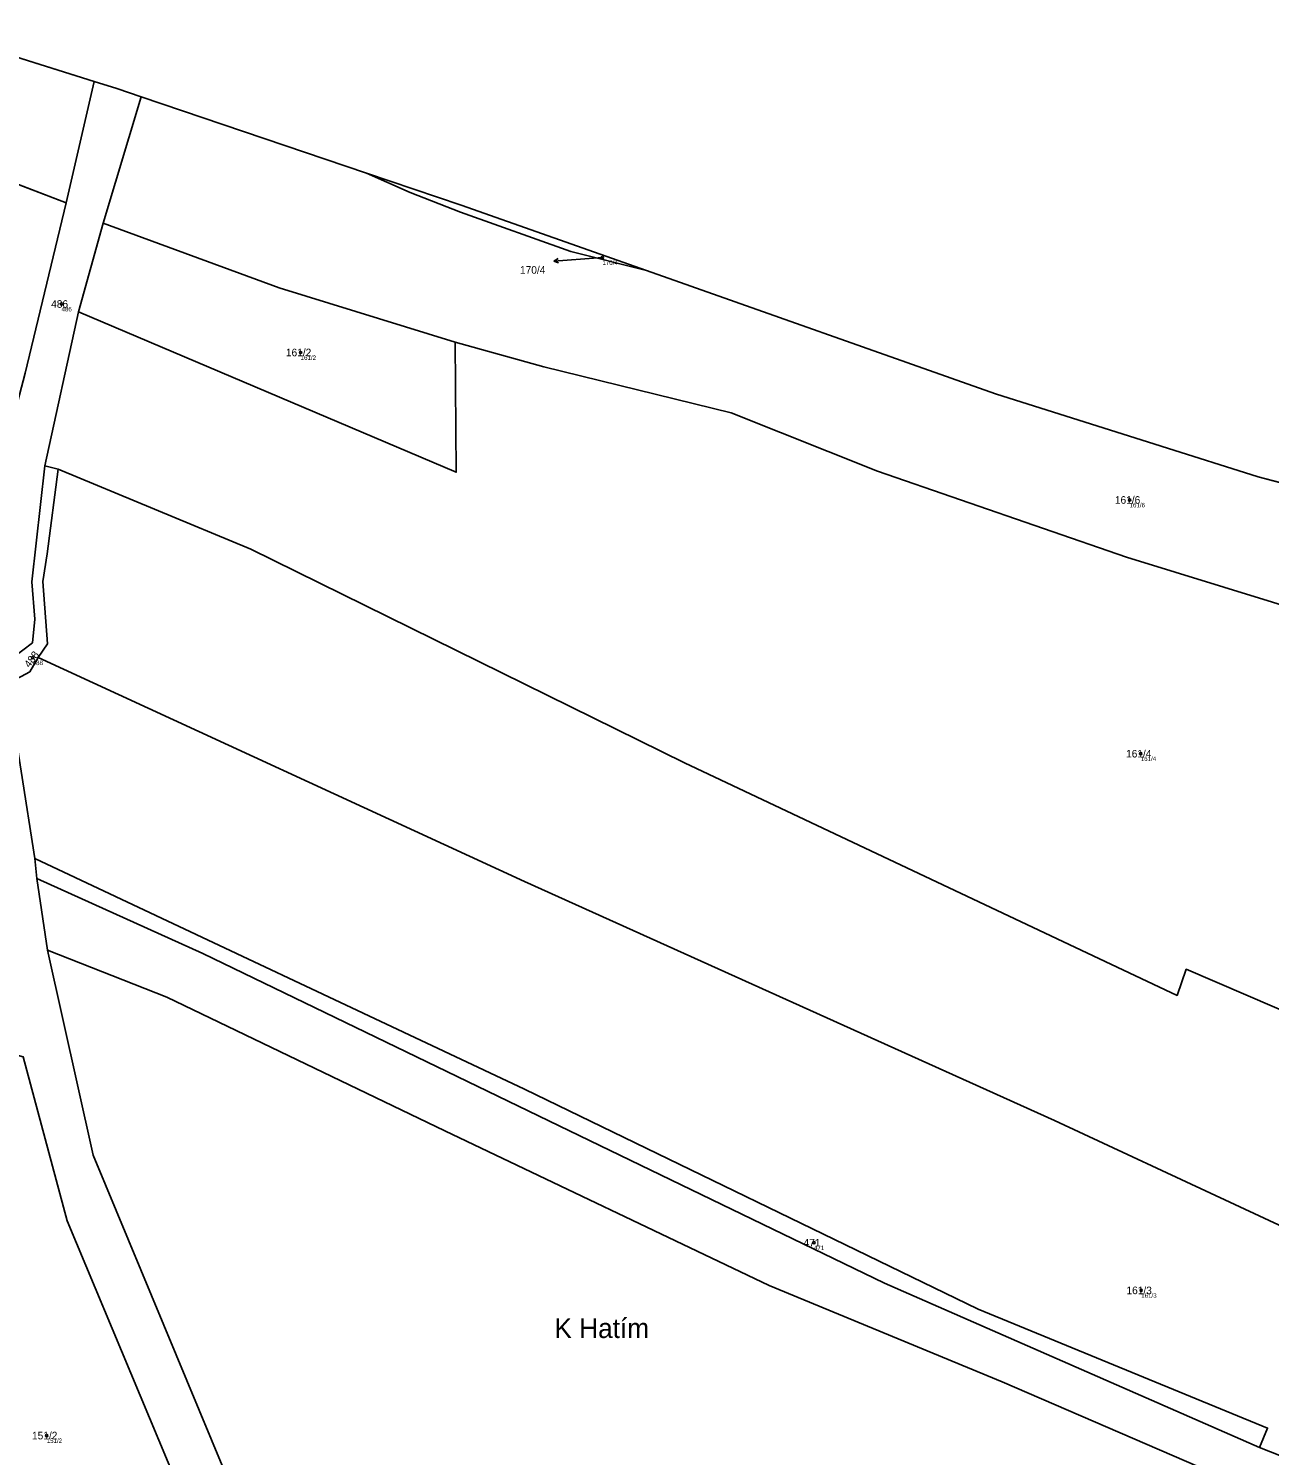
# Model space of a CAD drawing. Extents: x -700238 to -698499, y -1070626 to -1068006.
# Drawn here: x -700094 to -699815.7, y -1068332.5 to -1068012.6 of the extents above; entities that cross this region are included whole.
import ezdxf

# ---------------------------------------------------------------- set-up
doc = ezdxf.new("R2010")
doc.units = 0
for name, color, linetype in [('Definiční body', 7, 'Continuous'), ('Hranice parcel', 7, 'Continuous'), ('Parcelní čísla', 7, 'Continuous'), ('Polygon ku', 7, 'Continuous'), ('Polygon parcely', 7, 'Continuous'), ('Pop  PČ popisy', 7, 'Continuous')]:
    doc.layers.add(name, color=color, linetype=linetype)

msp = doc.modelspace()

# ---------------------------------------------------------------- linework, layer by layer
at = {"layer": 'Definiční body'}
for centre in [(-699965.3, -1068063.93994), (-700086.61, -1068074.34994), (-700032.98, -1068085.22994), (-699847.05, -1068118.28994), (-700093.08, -1068153.66994), (-699844.55, -1068175.18994), (-699917.85, -1068284.82994), (-699844.45, -1068295.52994), (-700089.93, -1068328.07994)]:
    msp.add_circle(centre, 0.25, dxfattribs=at)
at = {"layer": 'Hranice parcel'}
for p, q in [((-700079.26, -1068024.45), (-700117.11, -1068012.59)), ((-700079.26, -1068024.45), (-700085.54, -1068051.67)), ((-700077.24, -1068056.21), (-700068.77, -1068027.88)), ((-700068.77, -1068027.88), (-700018.24, -1068045.01)), ((-700085.54, -1068051.67), (-700125.51, -1068036.4)), ((-699996.96, -1068052.22), (-700018.24, -1068045.01)), ((-699955.42, -1068066.88), (-699996.96, -1068052.22)), ((-700082.81, -1068076.08), (-700077.24, -1068056.21)), ((-700090.39, -1068110.64), (-700082.81, -1068076.08)), ((-699818.2, -1068113.11), (-699840.01, -1068106.22)), ((-700087.38, -1068111.39), (-700090.39, -1068110.64)), ((-699778.25, -1068123.74), (-699818.2, -1068113.11)), ((-700092.58, -1068198.68), (-700098.76, -1068159.5)), ((-700092.18, -1068203.16), (-700092.58, -1068198.68)), ((-700089.79, -1068219.21), (-700092.18, -1068203.16))]:
    msp.add_line(p, q, dxfattribs=at)
for points in [[(-700068.77, -1068027.88), (-700074.2, -1068026.04), (-700079.26, -1068024.45)], [(-700018.24, -1068045.01), (-700008.41, -1068049.32), (-699997.14, -1068053.76), (-699972.36, -1068062.6), (-699955.42, -1068066.88)], [(-700099.51, -1068107.86), (-700094.74, -1068089.83), (-700085.54, -1068051.67)], [(-699998.31, -1068082.9), (-700037.79, -1068070.76), (-700077.24, -1068056.21)], [(-699955.42, -1068066.88), (-699877.11, -1068094.51), (-699840.01, -1068106.22)], [(-700082.81, -1068076.08), (-699998.06, -1068112.08), (-699998.31, -1068082.9)], [(-699612.1, -1068205.01), (-699704.91, -1068175.15), (-699847.75, -1068131.11), (-699903.56, -1068111.83), (-699936.42, -1068098.78), (-699978.4, -1068088.46), (-699998.31, -1068082.9)], [(-700099.66, -1068155.28), (-700093.15, -1068150.31), (-700092.59, -1068145.04), (-700093.29, -1068136.63), (-700090.39, -1068110.64)], [(-700091.82, -1068153.6), (-700089.78, -1068150.52), (-700090.77, -1068136.56), (-700089.86, -1068130.36), (-700087.38, -1068111.39)], [(-699647.05, -1068296.11), (-699722.11, -1068270.77), (-699760.47, -1068255.26), (-699834.34, -1068223.51), (-699836.42, -1068229.4), (-699946.86, -1068177.24), (-700044.14, -1068129.31), (-700087.38, -1068111.39)], [(-700098.76, -1068159.5), (-700093.72, -1068156.82), (-700091.82, -1068153.6)], [(-700091.82, -1068153.6), (-699982.79, -1068203.82), (-699863.89, -1068257.44), (-699783, -1068295.12), (-699698.72, -1068329.85), (-699635.57, -1068348.43), (-699608.73, -1068359.75)], [(-700092.58, -1068198.68), (-699982.77, -1068250.43), (-699881.04, -1068299.73), (-699816.11, -1068326.4), (-699817.93, -1068330.74)], [(-699817.93, -1068330.74), (-699901.99, -1068293.89), (-700054.94, -1068220), (-700092.18, -1068203.16)], [(-700047.78, -1068341.46), (-700079.51, -1068265.19), (-700089.79, -1068219.21)], [(-699627.99, -1068411.98), (-699659.02, -1068402.7), (-699710.69, -1068385.66), (-699740.56, -1068374.38), (-699875.66, -1068316.05), (-699927.93, -1068294.45), (-700000.63, -1068259.75), (-700062.96, -1068229.76), (-700089.79, -1068219.21)], [(-700040.88, -1068407.88), (-700044.5, -1068383.96), (-700052.63, -1068358.24), (-700085.32, -1068279.92), (-700095.19, -1068243.17)], [(-699623.95, -1068401.12), (-699708.94, -1068373.65), (-699817.93, -1068330.74)]]:
    msp.add_lwpolyline(points, dxfattribs=at)
at = {"layer": 'Polygon ku'}
msp.add_lwpolyline([(-699778.25, -1068123.74), (-699818.2, -1068113.11), (-699840.01, -1068106.22), (-699877.11, -1068094.51), (-699955.42, -1068066.88), (-699996.96, -1068052.22), (-700018.24, -1068045.01), (-700068.77, -1068027.88), (-700074.2, -1068026.04), (-700079.26, -1068024.45), (-700117.11, -1068012.59)], dxfattribs=at)
at = {"layer": 'Polygon parcely'}
for points in [[(-700079.26, -1068024.45), (-700117.11, -1068012.59), (-700126.53, -1068012.95), (-700125.51, -1068036.4), (-700085.54, -1068051.67)], [(-700068.77, -1068027.88), (-700074.2, -1068026.04), (-700079.26, -1068024.45), (-700085.54, -1068051.67), (-700094.74, -1068089.83), (-700099.51, -1068107.86), (-700107.22, -1068133.46), (-700099.66, -1068155.28), (-700093.15, -1068150.31), (-700092.59, -1068145.04), (-700093.29, -1068136.63), (-700090.39, -1068110.64), (-700082.81, -1068076.08), (-700077.24, -1068056.21)], [(-700106.82, -1068093.51), (-700104.41, -1068104.21), (-700112.08, -1068105.44), (-700099.51, -1068107.86), (-700094.74, -1068089.83), (-700085.54, -1068051.67), (-700125.51, -1068036.4), (-700117.1, -1068078.28), (-700110.86, -1068077.16), (-700109.59, -1068083.76), (-700115.86, -1068084.98), (-700114, -1068095.05)], [(-699955.42, -1068066.88), (-699996.96, -1068052.22), (-700018.24, -1068045.01), (-700008.41, -1068049.32), (-699997.14, -1068053.76), (-699972.36, -1068062.6)], [(-699998.31, -1068082.9), (-700037.79, -1068070.76), (-700077.24, -1068056.21), (-700082.81, -1068076.08), (-699998.06, -1068112.08)], [(-699847.75, -1068131.11), (-699903.56, -1068111.83), (-699936.42, -1068098.78), (-699978.4, -1068088.46), (-699998.31, -1068082.9), (-699998.06, -1068112.08), (-700082.81, -1068076.08), (-700090.39, -1068110.64), (-700087.38, -1068111.39), (-700044.14, -1068129.31), (-699946.86, -1068177.24), (-699836.42, -1068229.4), (-699834.34, -1068223.51), (-699760.47, -1068255.26), (-699722.11, -1068270.77), (-699647.05, -1068296.11), (-699612.1, -1068205.01), (-699704.91, -1068175.15)], [(-700091.82, -1068153.6), (-700089.78, -1068150.52), (-700090.77, -1068136.56), (-700089.86, -1068130.36), (-700087.38, -1068111.39), (-700090.39, -1068110.64), (-700093.29, -1068136.63), (-700092.59, -1068145.04), (-700093.15, -1068150.31), (-700099.66, -1068155.28), (-700098.76, -1068159.5), (-700093.72, -1068156.82)], [(-699591.24, -1068317.17), (-699647.05, -1068296.11), (-699722.11, -1068270.77), (-699760.47, -1068255.26), (-699834.34, -1068223.51), (-699836.42, -1068229.4), (-699946.86, -1068177.24), (-700044.14, -1068129.31), (-700087.38, -1068111.39), (-700089.86, -1068130.36), (-700090.77, -1068136.56), (-700089.78, -1068150.52), (-700091.82, -1068153.6), (-699982.79, -1068203.82), (-699863.89, -1068257.44), (-699783, -1068295.12), (-699698.72, -1068329.85), (-699635.57, -1068348.43), (-699608.73, -1068359.75)], [(-699881.04, -1068299.73), (-699816.11, -1068326.4), (-699817.93, -1068330.74), (-699708.94, -1068373.65), (-699623.95, -1068401.12), (-699608.73, -1068359.75), (-699635.57, -1068348.43), (-699698.72, -1068329.85), (-699783, -1068295.12), (-699863.89, -1068257.44), (-699982.79, -1068203.82), (-700091.82, -1068153.6), (-700093.72, -1068156.82), (-700098.76, -1068159.5), (-700092.58, -1068198.68), (-699982.77, -1068250.43)], [(-700092.18, -1068203.16), (-700054.94, -1068220), (-699901.99, -1068293.89), (-699817.93, -1068330.74), (-699816.11, -1068326.4), (-699881.04, -1068299.73), (-699982.77, -1068250.43), (-700092.58, -1068198.68)], [(-699708.94, -1068373.65), (-699817.93, -1068330.74), (-699901.99, -1068293.89), (-700054.94, -1068220), (-700092.18, -1068203.16), (-700089.79, -1068219.21), (-700062.96, -1068229.76), (-700000.63, -1068259.75), (-699927.93, -1068294.45), (-699875.66, -1068316.05), (-699740.56, -1068374.38), (-699710.69, -1068385.66), (-699659.02, -1068402.7), (-699627.99, -1068411.98), (-699623.95, -1068401.12)], [(-700000.63, -1068259.75), (-700062.96, -1068229.76), (-700089.79, -1068219.21), (-700079.51, -1068265.19), (-700047.78, -1068341.46), (-700005.69, -1068352.12), (-699955.8, -1068368.76), (-699866.66, -1068407.29), (-699790, -1068441.55), (-699746.59, -1068459.53), (-699655.97, -1068487.17), (-699627.99, -1068411.98), (-699659.02, -1068402.7), (-699710.69, -1068385.66), (-699740.56, -1068374.38), (-699875.66, -1068316.05), (-699927.93, -1068294.45)], [(-700044.5, -1068383.96), (-700052.63, -1068358.24), (-700085.32, -1068279.92), (-700095.19, -1068243.17), (-700097.88, -1068242.45), (-700122.52, -1068345.31), (-700127.75, -1068351.76), (-700139.55, -1068349.38), (-700128.39, -1068373.62), (-700040.88, -1068407.88)]]:
    msp.add_lwpolyline(points, close=True, dxfattribs=at)
for points in [[(-699778.25, -1068123.74), (-699818.2, -1068113.11), (-699840.01, -1068106.22), (-699877.11, -1068094.51), (-699955.42, -1068066.88), (-699972.36, -1068062.6), (-699997.14, -1068053.76), (-700008.41, -1068049.32), (-700018.24, -1068045.01), (-700068.77, -1068027.88), (-700077.24, -1068056.21), (-700037.79, -1068070.76), (-699998.31, -1068082.9), (-699978.4, -1068088.46), (-699936.42, -1068098.78), (-699903.56, -1068111.83), (-699847.75, -1068131.11), (-699704.91, -1068175.15)], [(-700047.78, -1068341.46), (-700079.51, -1068265.19), (-700089.79, -1068219.21), (-700092.18, -1068203.16), (-700092.58, -1068198.68), (-700098.76, -1068159.5)], [(-700095.19, -1068243.17), (-700085.32, -1068279.92), (-700052.63, -1068358.24)]]:
    msp.add_lwpolyline(points, dxfattribs=at)
at = {"layer": 'Pop  PČ popisy'}
for p, q in [((-699976.184, -1068064.719), (-699975.22, -1068064.15)), ((-699965.3, -1068063.94), (-699973.19, -1068064.51)), ((-699973.19, -1068064.51), (-699976.184, -1068064.719)), ((-699976.184, -1068064.719), (-699975.15, -1068065.149))]:
    msp.add_line(p, q, dxfattribs=at)

# ---------------------------------------------------------------- texts
at = {"layer": 'Definiční body'}
for s, p in [('170/4', (-699965.3, -1068065.596)), ('486', (-700086.61, -1068076.006)), ('161/2', (-700032.98, -1068086.886)), ('161/6', (-699847.05, -1068119.946)), ('488', (-700093.08, -1068155.326)), ('161/4', (-699844.55, -1068176.846)), ('471', (-699917.85, -1068286.486)), ('161/3', (-699844.45, -1068297.186)), ('151/2', (-700089.93, -1068329.736))]:
    msp.add_text(s, height=0.999996, dxfattribs=at).set_placement(p)
at = {"layer": 'Parcelní čísla'}
for s, p in [('170/4', (-699983.777, -1068067.568)), ('486', (-700088.935, -1068075.2)), ('161/2', (-700036.278, -1068086.08)), ('161/6', (-699850.348, -1068119.14)), ('161/4', (-699847.848, -1068176.04)), ('471', (-699920.175, -1068285.68)), ('161/3', (-699847.748, -1068296.38)), ('151/2', (-700093.228, -1068328.93))]:
    msp.add_text(s, height=1.699998, dxfattribs=at).set_placement(p)
msp.add_text('488', height=1.699998, rotation=53, dxfattribs=at).set_placement((-700093.8, -1068156.038))
at = {"layer": 'Pop  PČ popisy'}
msp.add_text('K Hatím', height=4.399998, dxfattribs=at).set_placement((-699976.071, -1068306.21))

doc.saveas('drawing.dxf')
